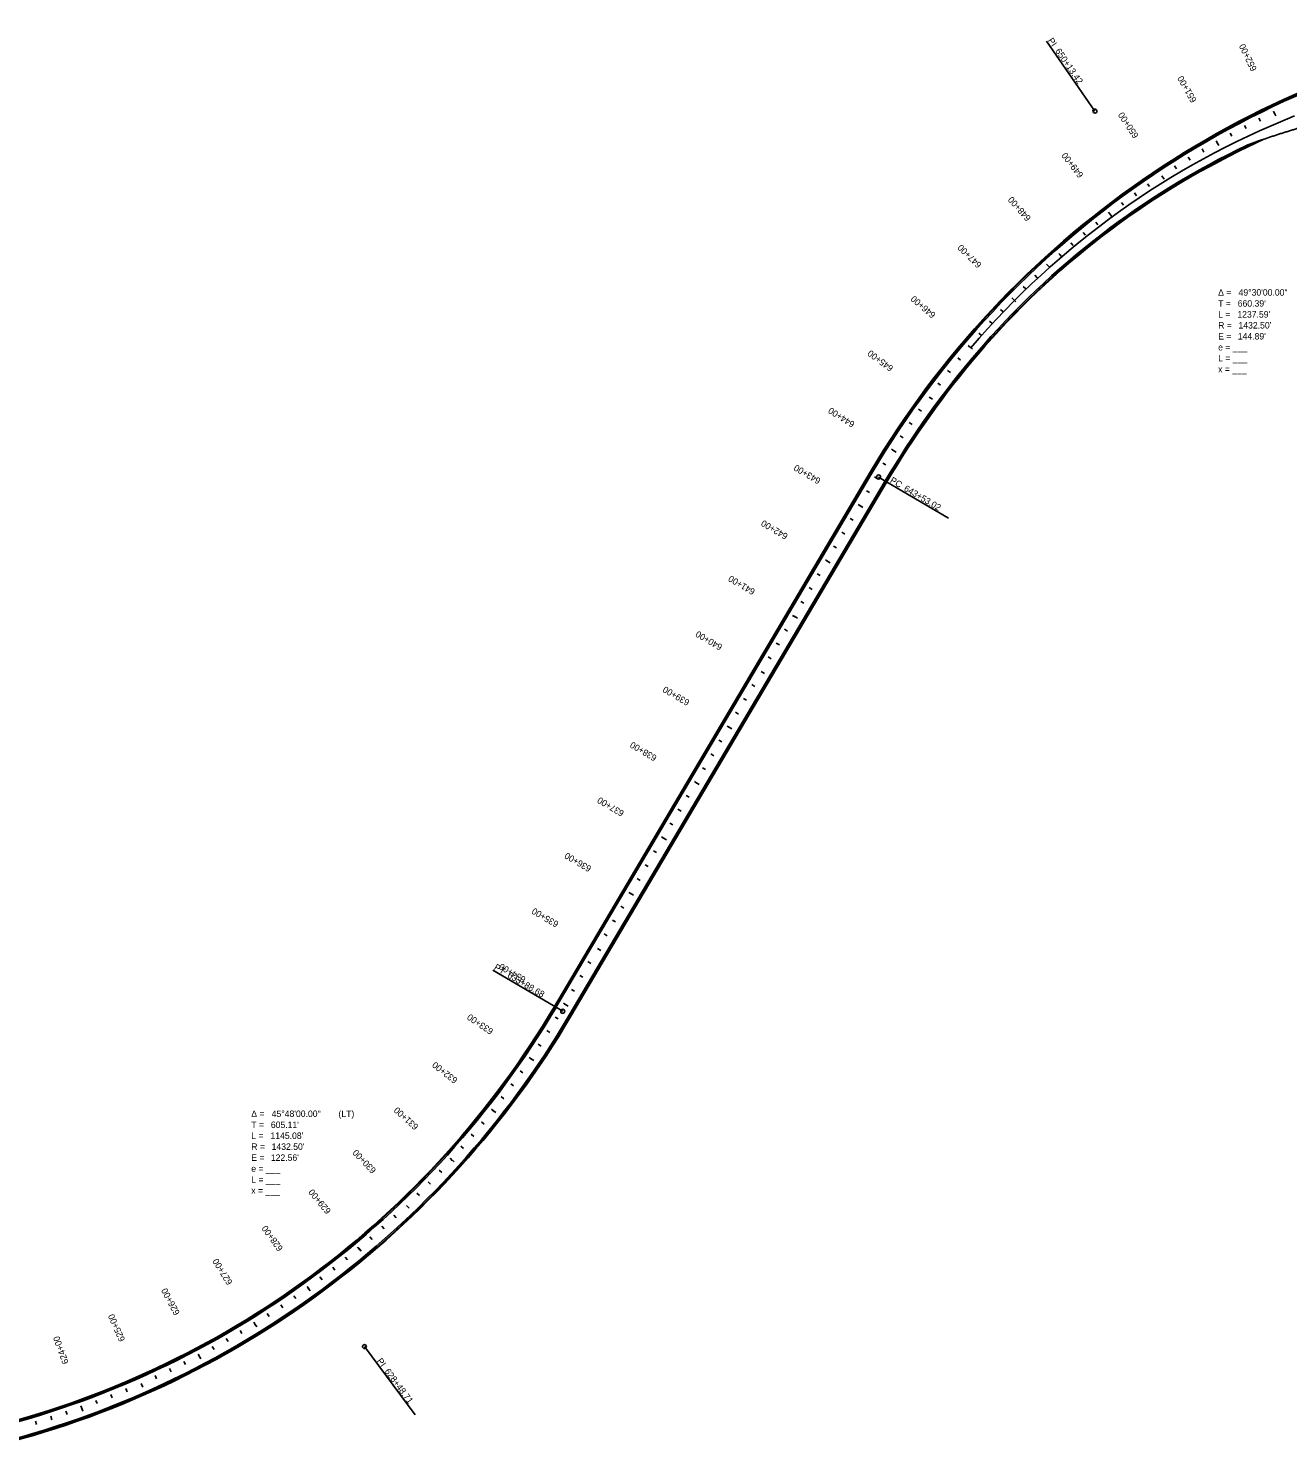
# Model space of a CAD drawing. Extents: x 22755720 to 22802976, y 6232173 to 6285384.
# Drawn here: x 22797050 to 22799005, y 6282425 to 6284630 of the extents above; entities that cross this region are included whole.
import ezdxf

# ---------------------------------------------------------------- set-up
doc = ezdxf.new("R2010")
doc.units = 0
for name, color, linetype in [('Culvert', 7, 'Continuous'), ('Draft_3', 7, 'Continuous'), ('dsnCellElements', 7, 'Continuous'), ('dsnTextEven', 7, 'Continuous'), ('dsnTextNote', 7, 'Continuous'), ('TextNonPlot', 7, 'Continuous')]:
    doc.layers.add(name, color=color, linetype=linetype)

msp = doc.modelspace()

# ---------------------------------------------------------------- linework, layer by layer
at = {"layer": 'Culvert'}
for p, q in [((22798963.3, 6284485.6), (22798960.8, 6284490.5)), ((22798984.4, 6284499.3), (22798987, 6284493.8)), ((22798918.9, 6284462.5), (22798916.3, 6284467.3)), ((22798941, 6284474.2), (22798938.5, 6284479.1)), ((22798875.4, 6284437.8), (22798872.6, 6284442.6)), ((22798895.6, 6284453), (22798898.6, 6284447.7)), ((22798854, 6284425), (22798851.1, 6284429.6)), ((22798810.2, 6284400.6), (22798813.5, 6284395.5)), ((22798832.8, 6284411.7), (22798829.9, 6284416.3)), ((22798791.1, 6284384.1), (22798788, 6284388.6)), ((22798750.4, 6284355), (22798747.2, 6284359.4)), ((22798770.7, 6284369.7), (22798767.5, 6284374.2)), ((22798728.6, 6284342.4), (22798732.4, 6284337.5)), ((22798691.4, 6284308.8), (22798687.9, 6284313)), ((22798710.8, 6284324.6), (22798707.4, 6284328.8)), ((22798672.2, 6284292.7), (22798668.7, 6284296.9)), ((22798651.4, 6284278.6), (22798655.4, 6284274)), ((22798616.5, 6284242.5), (22798612.8, 6284246.5)), ((22798634.8, 6284259.6), (22798631.1, 6284263.6)), ((22798598.6, 6284225.1), (22798594.7, 6284229)), ((22798578.7, 6284209.6), (22798583.1, 6284205.3)), ((22798563.5, 6284189.5), (22798559.6, 6284193.2)), ((22798529.8, 6284152.6), (22798525.7, 6284156.2)), ((22798546.5, 6284171.2), (22798542.5, 6284174.9)), ((22798511.1, 6284135.7), (22798515.7, 6284131.7)), ((22798497.3, 6284114.5), (22798493.1, 6284118)), ((22798481.6, 6284095.1), (22798477.3, 6284098.5)), ((22798466.2, 6284075.4), (22798461.9, 6284078.7)), ((22798448.7, 6284057.2), (22798453.7, 6284053.6)), ((22798436.5, 6284035.2), (22798432.1, 6284038.4)), ((22798422.2, 6284014.7), (22798417.7, 6284017.8)), ((22798408.2, 6283994), (22798403.7, 6283997)), ((22798392, 6283974.6), (22798397.2, 6283971.3)), ((22798381.4, 6283951.8), (22798376.7, 6283954.6)), ((22798355.8, 6283908.8), (22798351.1, 6283911.6)), ((22798368.5, 6283930.3), (22798363.8, 6283933.1)), ((22798330.4, 6283865.8), (22798325.7, 6283868.6)), ((22798340.5, 6283888.9), (22798345.7, 6283885.7)), ((22798317.6, 6283844.3), (22798312.9, 6283847)), ((22798304.9, 6283822.7), (22798300.2, 6283825.5)), ((22798289.6, 6283802.8), (22798294.8, 6283799.7)), ((22798279.5, 6283779.7), (22798274.8, 6283782.5)), ((22798266.8, 6283758.2), (22798262.1, 6283761)), ((22798254, 6283736.7), (22798249.3, 6283739.4)), ((22798238.7, 6283716.7), (22798244, 6283713.6)), ((22798228.6, 6283693.6), (22798223.9, 6283696.4)), ((22798215.9, 6283672.1), (22798211.2, 6283674.9)), ((22798203.2, 6283650.6), (22798198.5, 6283653.3)), ((22798187.8, 6283630.6), (22798193.1, 6283627.5)), ((22798177.7, 6283607.5), (22798173, 6283610.3)), ((22798165, 6283586), (22798160.3, 6283588.8)), ((22798152.3, 6283564.5), (22798147.6, 6283567.3)), ((22798136.9, 6283544.5), (22798142.2, 6283541.4)), ((22798126.8, 6283521.4), (22798122.1, 6283524.2)), ((22798114.1, 6283499.9), (22798109.4, 6283502.7)), ((22798101.4, 6283478.4), (22798096.7, 6283481.2)), ((22798086, 6283458.4), (22798091.3, 6283455.3)), ((22798075.9, 6283435.4), (22798071.2, 6283438.1)), ((22798063.2, 6283413.8), (22798058.5, 6283416.6)), ((22798050.5, 6283392.3), (22798045.8, 6283395.1)), ((22798035.1, 6283372.3), (22798040.4, 6283369.2)), ((22798025.1, 6283349.3), (22798020.4, 6283352)), ((22798012.3, 6283327.7), (22798007.6, 6283330.5)), ((22797999.6, 6283306.2), (22797994.9, 6283309)), ((22797984.3, 6283286.3), (22797989.5, 6283283.1)), ((22797974.2, 6283263.2), (22797969.5, 6283266)), ((22797961.5, 6283241.7), (22797956.8, 6283244.4)), ((22797948.7, 6283220.1), (22797944, 6283222.9)), ((22797933.4, 6283200.2), (22797938.6, 6283197.1)), ((22797923.3, 6283177.1), (22797918.6, 6283179.9)), ((22797910.6, 6283155.6), (22797905.9, 6283158.4)), ((22797897.8, 6283134.1), (22797893.1, 6283136.8)), ((22797882.5, 6283114.1), (22797887.8, 6283111)), ((22797872.3, 6283091), (22797867.7, 6283093.9)), ((22797845.8, 6283048.7), (22797841.2, 6283051.7)), ((22797859.2, 6283069.8), (22797854.6, 6283072.7)), ((22797829.4, 6283029.6), (22797834.4, 6283026.2)), ((22797817.7, 6283007.3), (22797813.2, 6283010.5)), ((22797803.1, 6282987), (22797798.7, 6282990.2)), ((22797788.2, 6282966.9), (22797783.9, 6282970.2)), ((22797770.5, 6282949), (22797775.4, 6282945.3)), ((22797757.3, 6282927.6), (22797753.1, 6282931.1)), ((22797741.4, 6282908.4), (22797737.2, 6282911.9)), ((22797725.1, 6282889.4), (22797721, 6282893)), ((22797691.6, 6282852.3), (22797687.6, 6282856)), ((22797706.2, 6282872.8), (22797710.8, 6282868.7)), ((22797674.3, 6282834.2), (22797670.4, 6282838)), ((22797656.8, 6282816.4), (22797652.9, 6282820.3)), ((22797636.8, 6282801.2), (22797641, 6282796.7)), ((22797602.2, 6282764.9), (22797598.6, 6282769)), ((22797620.7, 6282781.8), (22797617, 6282785.8)), ((22797583.5, 6282748.4), (22797579.9, 6282752.5)), ((22797545.1, 6282716.4), (22797541.7, 6282720.6)), ((22797562.5, 6282734.6), (22797566.4, 6282729.9)), ((22797525.5, 6282700.8), (22797522.2, 6282705.2)), ((22797505.6, 6282685.7), (22797502.4, 6282690)), ((22797465.1, 6282656.4), (22797462, 6282660.9)), ((22797483.7, 6282673.3), (22797487.3, 6282668.4)), ((22797423.6, 6282628.5), (22797420.6, 6282633.1)), ((22797444.5, 6282642.3), (22797441.4, 6282646.8)), ((22797400.9, 6282617.7), (22797404.1, 6282612.5)), ((22797359.6, 6282589.5), (22797356.9, 6282594.2)), ((22797381.1, 6282602.1), (22797378.3, 6282606.8)), ((22797314.4, 6282568), (22797317.2, 6282562.6)), ((22797337.8, 6282577.2), (22797335.1, 6282582)), ((22797271.2, 6282542.7), (22797268.8, 6282547.7)), ((22797293.6, 6282553.9), (22797291.1, 6282558.7)), ((22797224.6, 6282524.5), (22797227.1, 6282518.9)), ((22797248.6, 6282532), (22797246.3, 6282537)), ((22797179.8, 6282502.3), (22797177.7, 6282507.4)), ((22797202.9, 6282511.8), (22797200.8, 6282516.8)), ((22797109.5, 6282476.2), (22797107.7, 6282481.4)), ((22797132, 6282487.4), (22797134.1, 6282481.6)), ((22797156.5, 6282493.2), (22797154.5, 6282498.3)), ((22797061.9, 6282460.9), (22797060.3, 6282466.1)), ((22797085.7, 6282468.3), (22797084.1, 6282473.5))]:
    msp.add_line(p, q, dxfattribs=at)
at = {"layer": 'Draft_3'}
for p, q in [((22798706.1, 6284501.4), (22798631, 6284610)), ((22798631, 6284610), (22798631, 6284610)), ((22798370.1, 6283932.9), (22798478.5, 6283868.8)), ((22798478.5, 6283868.8), (22798478.5, 6283868.8)), ((22797879.4, 6283102.8), (22797770.9, 6283166.9)), ((22797770.9, 6283166.9), (22797770.9, 6283166.9)), ((22797571.5, 6282581.9), (22797650, 6282475.8)), ((22797650, 6282475.8), (22797650, 6282475.8))]:
    msp.add_line(p, q, dxfattribs=at)
for centre in [(22798706.1, 6284501.4), (22798370.1, 6283932.9), (22797879.4, 6283102.8), (22797571.5, 6282581.9)]:
    msp.add_circle(centre, 3.12, dxfattribs=at)
at = {"layer": 'dsnCellElements'}
for p, q in [((22798943.2, 6284446.8), (22798960.4, 6284455)), ((22798943.7, 6284445.9), (22798968.6, 6284457.8)), ((22797866.5, 6283110.4), (22798357.2, 6283940.6)), ((22797867.3, 6283109.9), (22798358, 6283940.1)), ((22797891.4, 6283095.7), (22798382.1, 6283925.8)), ((22797892.3, 6283095.2), (22798383, 6283925.3))]:
    msp.add_line(p, q, dxfattribs=at)
for centre, radius, start, end in [((22799603.2, 6283204), 1447.5, 99.9129, 149.4129), ((22799603.2, 6283204), 1446.5, 99.9129, 149.4129), ((22799492.2, 6283298.7), 1272.5, 115.5556, 139.5346), ((22799492.2, 6283298.7), 1271.5, 115.5556, 139.5346), ((22799603.2, 6283204), 1418.5, 139.5346, 149.4129), ((22799603.2, 6283204), 1417.5, 139.5346, 149.4129), ((22796646.2, 6283831.7), 1417.5, 283.6129, 329.4129), ((22796646.2, 6283831.7), 1418.5, 283.6129, 329.4129), ((22796646.2, 6283831.7), 1446.5, 283.6129, 329.4129), ((22796646.2, 6283831.7), 1447.5, 283.6129, 329.4129)]:
    msp.add_arc(centre, radius, start, end, dxfattribs=at)
at = {"layer": 'dsnTextEven'}
msp.add_arc((22799492.2, 6283298.7), 1286.5, 111.725, 139.5346, dxfattribs=at)
at = {"layer": 'dsnTextNote'}
for p, q in [((22798985.7, 6284496.6), (22798983.4, 6284501.5)), ((22798897.1, 6284450.4), (22798894.4, 6284455.1)), ((22798810.2, 6284400.6), (22798813.5, 6284395.5)), ((22798730.5, 6284340), (22798727.2, 6284344.3)), ((22798653.4, 6284276.3), (22798649.8, 6284280.4)), ((22798580.9, 6284207.5), (22798577, 6284211.3)), ((22798513.4, 6284133.7), (22798509.2, 6284137.2)), ((22798448.7, 6284057.2), (22798453.7, 6284053.6)), ((22798394.6, 6283973), (22798390, 6283975.9)), ((22798343.1, 6283887.3), (22798338.4, 6283890.1)), ((22798292.2, 6283801.2), (22798287.5, 6283804)), ((22798241.3, 6283715.1), (22798236.6, 6283717.9)), ((22798187.8, 6283630.6), (22798193.1, 6283627.5)), ((22798139.5, 6283543), (22798134.8, 6283545.7)), ((22798088.7, 6283456.9), (22798084, 6283459.7)), ((22798037.8, 6283370.8), (22798033.1, 6283373.6)), ((22797986.9, 6283284.7), (22797982.2, 6283287.5)), ((22797933.4, 6283200.2), (22797938.6, 6283197.1)), ((22797885.1, 6283112.5), (22797880.4, 6283115.3)), ((22797831.9, 6283027.9), (22797827.4, 6283031)), ((22797772.9, 6282947.1), (22797768.7, 6282950.5)), ((22797708.5, 6282870.7), (22797704.5, 6282874.4)), ((22797636.8, 6282801.2), (22797641, 6282796.7)), ((22797564.4, 6282732.2), (22797560.9, 6282736.4)), ((22797485.5, 6282670.8), (22797482.3, 6282675.3)), ((22797402.5, 6282615.1), (22797399.6, 6282619.8)), ((22797315.8, 6282565.3), (22797313.2, 6282570.2)), ((22797224.6, 6282524.5), (22797227.1, 6282518.9)), ((22797133, 6282484.5), (22797131.2, 6282489.6))]:
    msp.add_line(p, q, dxfattribs=at)
at = {"layer": 'TextNonPlot'}
for p, q in [((22797869, 6283108.9), (22798359.7, 6283939.1)), ((22797869, 6283108.9), (22798359.7, 6283939.1)), ((22797889.7, 6283096.7), (22798380.4, 6283926.8))]:
    msp.add_line(p, q, dxfattribs=at)
for centre, radius, start, end in [((22799603.2, 6283204), 1444.5, 99.9129, 149.4129), ((22799603.2, 6283204), 1444.5, 99.9129, 149.4129), ((22799492.2, 6283298.7), 1274.5, 115.5556, 139.5346), ((22799603.2, 6283204), 1420.5, 139.5346, 149.4129), ((22796646.2, 6283831.7), 1420.5, 283.6129, 329.4129), ((22796646.2, 6283831.7), 1420.5, 283.6129, 329.4129), ((22796646.2, 6283831.7), 1444.5, 283.6129, 329.4129)]:
    msp.add_arc(centre, radius, start, end, dxfattribs=at)
msp.add_open_spline([(22798942.4, 6284448.6), (22798944.2, 6284449.3), (22798948, 6284450.6), (22798953.6, 6284452.6), (22798959.2, 6284454.6), (22798964.8, 6284456.5), (22798970.5, 6284458.5), (22798976.1, 6284460.3), (22798981.7, 6284462.2), (22798987.4, 6284464.1), (22798993, 6284465.9), (22798998.7, 6284467.7), (22799004.3, 6284469.4), (22799010, 6284471.2), (22799015.6, 6284472.9), (22799021.3, 6284474.6), (22799027, 6284476.3), (22799032.7, 6284477.9), (22799038.3, 6284479.5), (22799044, 6284481.1), (22799049.7, 6284482.7), (22799053.5, 6284483.7), (22799055.4, 6284484.2)], degree=3, dxfattribs=at)

# ---------------------------------------------------------------- texts
at = {"layer": 'Culvert'}
for s, rotation, p in [('652+00', 115.5364, (22798957.9, 6284566.4)), ('651+00', 119.5361, (22798864.5, 6284518.1)), ('650+00', 123.5358, (22798774.6, 6284463.4)), ('649+00', 127.5355, (22798688.8, 6284402.5)), ('648+00', 131.5352, (22798607.4, 6284335.8)), ('647+00', 135.5349, (22798530.9, 6284263.6)), ('646+00', 139.5346, (22798459.6, 6284186.2)), ('645+00', 143.5343, (22798393.9, 6284104)), ('644+00', 147.534, (22798334, 6284017.5)), ('643+00', 149.4129, (22798281.1, 6283929.8)), ('642+00', 149.4129, (22798230.2, 6283843.7)), ('641+00', 149.4129, (22798179.3, 6283757.6)), ('640+00', 149.4129, (22798128.4, 6283671.5)), ('639+00', 149.4129, (22798077.5, 6283585.4)), ('638+00', 149.4129, (22798026.6, 6283499.3)), ('637+00', 149.4129, (22797975.8, 6283413.3)), ('636+00', 149.4129, (22797924.9, 6283327.2)), ('635+00', 149.4129, (22797874, 6283241.1)), ('634+00', 149.4129, (22797823.1, 6283155)), ('633+00', 145.8658, (22797772.6, 6283074.1)), ('632+00', 141.8661, (22797717.1, 6282997.4)), ('631+00', 137.8663, (22797656.2, 6282924.7)), ('630+00', 133.8666, (22797590.5, 6282856.5)), ('629+00', 129.8669, (22797520.2, 6282793)), ('628+00', 125.8672, (22797445.6, 6282734.6)), ('627+00', 121.8675, (22797367.1, 6282681.5)), ('626+00', 117.8678, (22797285.2, 6282634)), ('625+00', 113.8681, (22797200.1, 6282592.3)), ('624+00', 109.8684, (22797112.3, 6282556.7))]:
    msp.add_text(s, height=10.02, rotation=rotation, dxfattribs=at).set_placement(p)
at = {"layer": 'Draft_3'}
for s, rotation, p in [('PI ', 304.6629, (22798632.4, 6284611)), ('650+13.42', 304.6629, (22798643.8, 6284594.6)), ('PC', 329.4129, (22798386.9, 6283925)), ('643+53.02', 329.4129, (22798408.4, 6283912.3)), ('PT', 329.4129, (22797771.8, 6283168.4)), ('633+88.68', 329.4129, (22797792.6, 6283156)), ('PI ', 306.5129, (22797590.2, 6282559.4)), ('628+48.71', 306.5129, (22797602.1, 6282543.3))]:
    msp.add_text(s, height=10.02, rotation=rotation, dxfattribs=at).set_placement(p)
for s, p in [('Δ = ', (22798897.5, 6284214.7)), ('49°30\'00.00"', (22798929.2, 6284214.7)), ('T = ', (22798897.5, 6284197.6)), ("660.39'", (22798927.9, 6284197.6)), ('L = ', (22798897.5, 6284180.6)), ("1237.59'", (22798927.3, 6284180.6)), ('R = ', (22798897.5, 6284163.6)), ('E = ', (22798897.5, 6284146.5)), ("144.89'", (22798928, 6284146.5)), ("1432.50'", (22798929.1, 6284163.6)), ('e = ___ ', (22798897.5, 6284129.5)), ('L = ___', (22798897.5, 6284112.5)), ('x = ___', (22798897.5, 6284095.4)), ('Δ = ', (22797395.7, 6282938.6)), ('45°48\'00.00"', (22797427.4, 6282938.6)), (' (LT)', (22797527.4, 6282938.6)), ('T = ', (22797395.7, 6282921.5)), ("605.11'", (22797426.1, 6282921.5)), ('L = ', (22797395.7, 6282904.5)), ('R = ', (22797395.7, 6282887.5)), ("1145.08'", (22797425.5, 6282904.5)), ("1432.50'", (22797427.3, 6282887.5)), ('E = ', (22797395.7, 6282870.4)), ("122.56'", (22797426.1, 6282870.4)), ('e = ___ ', (22797395.7, 6282853.4)), ('L = ___', (22797395.7, 6282836.4)), ('x = ___', (22797395.7, 6282819.3))]:
    msp.add_text(s, height=10.02, dxfattribs=at).set_placement(p)
at = {"layer": 'dsnTextNote'}
for s, rotation, p in [('650+00', 123.5358, (22798774.6, 6284463.4)), ('645+00', 143.5343, (22798393.9, 6284104)), ('640+00', 149.4129, (22798128.4, 6283671.5)), ('635+00', 149.4129, (22797874, 6283241.1)), ('630+00', 133.8666, (22797590.5, 6282856.5)), ('625+00', 113.8681, (22797200.1, 6282592.3))]:
    msp.add_text(s, height=10.02, rotation=rotation, dxfattribs=at).set_placement(p)

doc.saveas('drawing.dxf')
